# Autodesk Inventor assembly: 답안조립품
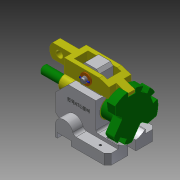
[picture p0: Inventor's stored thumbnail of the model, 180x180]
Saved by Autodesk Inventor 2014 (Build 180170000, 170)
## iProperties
Created: 2016-11
Part Number: 답안조립품
Document SubType Name: Assembly
Designer: user
Author: user
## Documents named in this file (8)
- C:\Users\user\Desktop\461108V1015\답안조립품.iam
- C:\Users\user\Desktop\461108V1015\본체.ipt
- C:\Users\user\Desktop\461108V1015\부시.ipt
- C:\Users\user\Desktop\461108V1015\분할축.ipt
- C:\Users\user\Desktop\461108V1015\분할대.ipt
- C:\Users\user\Desktop\461108V1015\와셔.ipt
- C:\Users\user\Desktop\461108V1015\원통형핀.ipt
- C:\Users\user\Desktop\461108V1015\클레비스핀.ipt
